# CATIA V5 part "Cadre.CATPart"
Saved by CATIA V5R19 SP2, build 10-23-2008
Part number: Cadre
Bounding box of the stored display mesh (mm): x -34 to 40, y -77.87 to 77.87, z -205.145 to 0
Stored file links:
  C:\Users\Romain\Documents\IFMA\2A\cours\S3\Projet CFAO-IAO\IAO\Catia\Cadre.CATPart
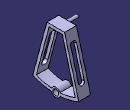
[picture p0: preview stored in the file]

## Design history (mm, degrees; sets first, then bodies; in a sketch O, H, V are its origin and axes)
Body1 (main body)
  Sketch1 "Esquisse.1" on yz-plane, origin (0, 0, 0), H (0, 1, 0), V (0, 0, 1)
    line L1 (-30, 0) -> (30, 0)
    point P1 (-30, 0)
    point P2 (30, 0)
    line L2 (30, 0) -> (77.8695, -178.6516)
    arc A1 centre (0, -3.0778) radius 192.0672 from (-77.8695, -178.6516) to (77.8695, -178.6516) ccw
    point P4 (0, -3.0778)
    line L3 (-30, 0) -> (-77.8695, -178.6516)
    line L4 (-22.3267, -10) -> (22.3267, -10)
    line L5 (-22.3267, -10) -> (-65.9443, -172.7829)
    point P8 (-65.9443, -172.7829)
    arc A2 centre (0, -3.0778) radius 182.0672 from (-65.9443, -172.7829) to (65.9443, -172.7829) ccw
    line L6 (22.3267, -10) -> (65.9443, -172.7829)
    length L1 = 60
    distance P2 V = 30
    angle L2 L1 = 75
    angle L3 L1 = 105
    distance L1 A1 = 195.145
    distance L4 L1 = 10
    distance A2 A1 = 10
    distance L2 L6 = 10
    distance L5 L3 = 10
    coincidence: P1 H, P4 V, A2 P8
    horizontal: L1 H, L4 H
  Pad1: profile Sketch1, direction (1, 0, 0), length 40
  Sketch2 "Esquisse.2" on end face of Pad1, origin (40, 0, 0), H (0, 1, 0), V (0, 0, 1)
    circle A1 centre (0, -5) radius 5
    point P1 (0, -5)
    reference projected line E1 (50, 0) -> (-50, 0) from edge [face of Pad1 from Sketch1.L1 | end face of Pad1]
    radius A1 = 5
    distance E1 P1 = 5
    coincidence: P1 V
  Pad2: profile Sketch2, direction (-1, 0, 0), length 74
  Sketch3 "Esquisse.4" on face of Pad2, origin (40, 0, 0), H (0, 1, 0), V (0, 0, 1)
    circle A1 centre (0, -190.145) radius 15
    point P1 (0, -190.145)
    reference projected arc E1 centre (0, -3.0778) radius 182.0672 from (-78.7339, -167.2406) to (78.7339, -167.2406) ccw from edge [end face of Pad1 | face of Pad1 from Sketch1.A2]
    radius A1 = 15
    distance P1 E1 = 5
    coincidence: P1 V
  Pad3: profile Sketch3, direction (-1, 0, 0), length 40
  Sketch4 on face of Pad3, origin (40, 0, 0), H (0, 1, 0), V (0, 0, 1)
    circle A1 centre (0, -190.145) radius 10
    point P1 (0, -190.145)
    reference projected arc E1 centre (0, -190.145) radius 15 from (13.9416, -184.6104) to (-13.9416, -184.6104) ccw from edge [face of Pad3 from Sketch3.A1 | face of Pad3]
    radius A1 = 10
    distance A1 E1 = 25
    coincidence: P1 V
  Pocket1: profile Sketch4, direction (-1, 0, 0), through (limit type 3)
  Sketch5 on face of Pad1 from Sketch1.L2, origin (0, 27.9904, 7.5), H (-1, 0, 0), V (0, -0.2588, 0.9659)
    line L1 (-30, -49.7646) -> (-30, -149.7646)
    point P1 (-30, -49.7646)
    point P2 (-30, -149.7646)
    line L2 (-10, -49.7646) -> (-10, -149.7646)
    arc A1 centre (-20, -49.7646) radius 10 from (-10, -49.7646) to (-30, -49.7646) ccw
    point P5 (-20, -49.7646)
    point P6 (-30, -49.7646)
    arc A2 centre (-20, -149.7646) radius 10 from (-30, -149.7646) to (-10, -149.7646) ccw
    point P8 (-30, -149.7646)
    reference projected line E1 (0, -7.7646) -> (-40, -7.7646) from edge [face of Pad1 from Sketch1.L1 | face of Pad1 from Sketch1.L2]
    reference projected line E2 (0, -192.7183) -> (0, -7.7646) from edge [start face of Pad1 | face of Pad1 from Sketch1.L2]
    radius A1 = 10
    length L2 = 100
    distance P5 E1 = 42
    distance L2 E2 = 10
    vertical: L1 V, L2 V
    tangency: A1 L2, A1 L1, A2 L2, A2 L1
    coincidence: P6 L1, P8 L1, P2 A2, P1 P6, P2 P8
  Pocket2: profile Sketch5, direction (0, -0.9659, -0.2588), through (limit type 6)
  Sketch6 on face of Pad1 from Sketch1.L3, origin (0, -27.9904, 7.5), H (1, 0, 0), V (0, 0.2588, 0.9659)
    line L1 (30, -149.7646) -> (30, -49.7646)
    line L2 (10, -149.7646) -> (10, -49.7646)
    point P3 (10, -149.7646)
    point P4 (10, -49.7646)
    arc A1 centre (20, -149.7646) radius 10 from (10, -149.7646) to (30, -149.7646) ccw
    point P6 (10, -149.7646)
    arc A2 centre (20, -49.7646) radius 10 from (30, -49.7646) to (10, -49.7646) ccw
    point P7 (20, -49.7646)
    point P8 (10, -49.7646)
    reference projected line E1 (0, -7.7646) -> (40, -7.7646) from edge [face of Pad1 from Sketch1.L3 | face of Pad1 from Sketch1.L1]
    reference projected line E2 (40, -7.7646) -> (40, -192.7183) from edge [face of Pad1 from Sketch1.L3 | end face of Pad1]
    radius A2 = 10
    length L1 = 100
    distance P7 E1 = 42
    distance L1 E2 = 10
    vertical: L1 V, L2 V
    tangency: A1 L1, A1 L2, A2 L1, A2 L2
    coincidence: P6 L2, P3 A1, P4 A2, P3 P6, P4 P8
  Pocket3: profile Sketch6, direction (0, 0.9659, -0.2588), through (limit type 6)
